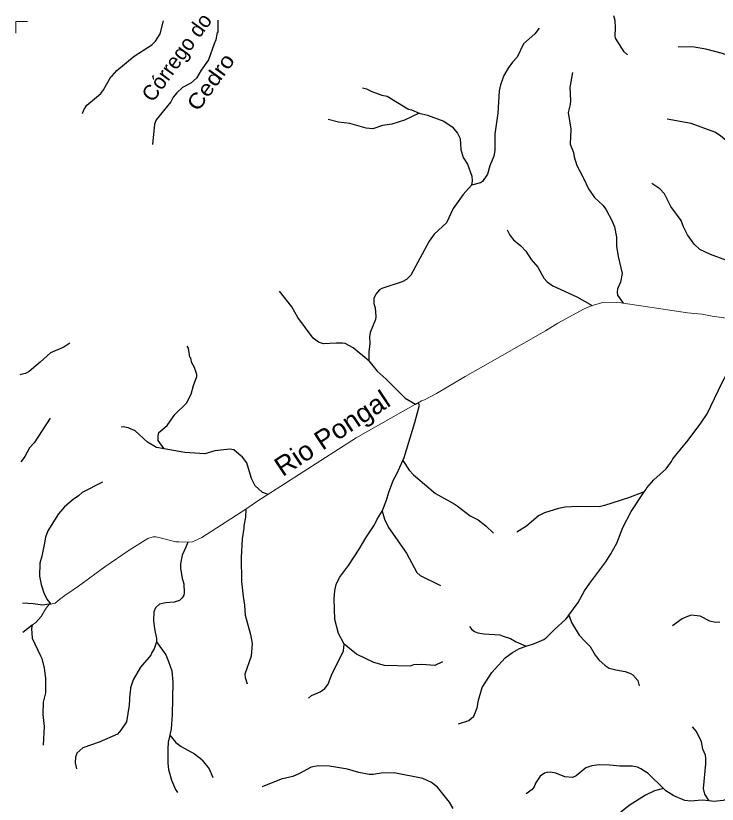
# Model space of a CAD drawing. Extents: x 317.8 to 344.1, y 7676.8 to 7704.8.
# Drawn here: x 317.793 to 321.463, y 7700.411 to 7704.539 of the extents above; entities that cross this region are included whole.
import ezdxf
from ezdxf.enums import TextEntityAlignment as Align

# ---------------------------------------------------------------- set-up
doc = ezdxf.new("R2010")
doc.units = 0
doc.header["$LTSCALE"] = 0.032
for name, color, linetype, lineweight in [('1', 7, 'Continuous', 13), ('63', 7, 'Continuous', 13), ('7', 7, 'Continuous', 25)]:
    doc.layers.add(name, color=color, linetype=linetype, lineweight=lineweight)
doc.layers.add('61', color=7, linetype='Continuous')

msp = doc.modelspace()

# ---------------------------------------------------------------- linework, layer by layer
at = {"layer": '1'}
for points in [[(320.8087, 7703.0226), (320.8641, 7703.0378), (320.9419, 7703.0395), (320.9717, 7703.035)], [(320.9717, 7703.035), (321.3079, 7702.9842), (321.3848, 7702.9759), (321.4363, 7702.9663), (321.7192, 7702.9269)], [(319.8989, 7702.5129), (319.9163, 7702.5228), (319.9317, 7702.5274), (319.9951, 7702.5615), (320.1438, 7702.6501), (320.2248, 7702.696), (320.5652, 7702.8889), (320.6296, 7702.9293), (320.7671, 7703.0045), (320.8087, 7703.0226)], [(319.1119, 7702.0323), (319.5748, 7702.3284), (319.8845, 7702.5047)], [(318.9971, 7701.9552), (319.0648, 7702.0022), (319.1119, 7702.0323)], [(318.6926, 7701.7822), (318.718, 7701.7847), (318.7659, 7701.8071), (318.9971, 7701.9552)], [(317.9761, 7701.4589), (317.9987, 7701.4639), (318.0212, 7701.4834), (318.0499, 7701.503), (318.1209, 7701.5517), (318.2595, 7701.6539), (318.3863, 7701.7416), (318.4847, 7701.8014), (318.5119, 7701.8104), (318.5274, 7701.8105), (318.6298, 7701.7845), (318.646, 7701.7839), (318.6926, 7701.7822)], [(317.9676, 7701.4577), (317.948, 7701.4315), (317.9265, 7701.393), (317.8972, 7701.362), (317.8781, 7701.3476)]]:
    msp.add_lwpolyline(points, dxfattribs=at)
at = {"layer": '63'}
msp.add_lwpolyline([(317.8546, 7704.5086), (317.793, 7704.5086), (317.793, 7704.4479)], dxfattribs=at)
at = {"layer": '7'}
for p, q in [((319.8845, 7702.5047), (319.8989, 7702.5129)), ((317.9761, 7701.4589), (317.9676, 7701.4577)), ((317.8781, 7701.3476), (317.8292, 7701.3107))]:
    msp.add_line(p, q, dxfattribs=at)
for points in [[(318.1428, 7704.0274), (318.1494, 7704.0465), (318.1642, 7704.0708), (318.215, 7704.1132), (318.2377, 7704.1322), (318.2523, 7704.1511), (318.2906, 7704.219), (318.2966, 7704.2255), (318.3218, 7704.2528), (318.4133, 7704.328), (318.5049, 7704.3878), (318.5233, 7704.407), (318.5477, 7704.4455), (318.5665, 7704.5133)], [(318.8502, 7704.5163), (318.8509, 7704.4524), (318.8476, 7704.451), (318.8402, 7704.4125), (318.8304, 7704.393), (318.8012, 7704.3085), (318.7633, 7704.2544), (318.7383, 7704.2121), (318.7097, 7704.1869), (318.6658, 7704.164), (318.6362, 7704.1362), (318.6173, 7704.1132), (318.604, 7704.089), (318.5276, 7703.994), (318.5192, 7703.9708), (318.5079, 7703.866)], [(320.9937, 7704.3354), (320.976, 7704.3499), (320.9305, 7704.4221), (320.9284, 7704.4316), (320.9317, 7704.476), (320.93, 7704.514), (320.9228, 7704.5386)], [(320.531, 7704.4749), (320.509, 7704.4441), (320.4496, 7704.3918), (320.4159, 7704.3231), (320.3916, 7704.2966), (320.3687, 7704.2648), (320.347, 7704.2264), (320.3296, 7704.1772), (320.3227, 7704.1461), (320.3149, 7704.0297), (320.2993, 7703.9192), (320.3001, 7703.8329), (320.2935, 7703.8033), (320.2729, 7703.7537), (320.2604, 7703.7093), (320.2358, 7703.6721), (320.2243, 7703.6647), (320.1772, 7703.6514)], [(322.3312, 7704.2681), (322.2484, 7704.2923), (322.1969, 7704.2991), (322.1875, 7704.3003), (321.904, 7704.2824), (321.7836, 7704.2898), (321.6788, 7704.2874), (321.6061, 7704.2973), (321.4911, 7704.341), (321.4044, 7704.3647), (321.3432, 7704.3753), (321.2586, 7704.3771)], [(320.7068, 7704.2426), (320.6913, 7704.1638), (320.6953, 7704.0959), (320.6936, 7704.0747), (320.6832, 7704.033), (320.6969, 7703.9454), (320.6946, 7703.8665), (320.712, 7703.8232), (320.7151, 7703.8009), (320.7281, 7703.7556), (320.7601, 7703.696), (320.7638, 7703.6891), (320.789, 7703.6337), (320.8211, 7703.5871), (320.8656, 7703.5456), (320.8825, 7703.5239), (320.9121, 7703.4674), (320.9249, 7703.434), (320.9365, 7703.3798), (320.9366, 7703.3334), (320.9445, 7703.2795), (320.9659, 7703.1891), (320.9577, 7703.1451), (320.941, 7703.1093), (320.9389, 7703.0921), (320.9415, 7703.0768), (320.9717, 7703.035)], [(319.6067, 7704.1613), (319.6284, 7704.157), (319.6552, 7704.1432), (319.7079, 7704.1239), (319.7359, 7704.1175), (319.8449, 7704.0522), (319.8472, 7704.0508), (319.8627, 7704.0474), (319.9038, 7704.0292)], [(319.9038, 7704.0292), (319.8629, 7704.0095), (319.8263, 7703.9919), (319.7611, 7703.9713), (319.7114, 7703.9639), (319.6606, 7703.9467), (319.6255, 7703.9501), (319.5403, 7703.975), (319.4823, 7703.9817), (319.4281, 7703.9956)], [(319.9038, 7704.0292), (319.9473, 7704.019), (320.0331, 7703.9867), (320.0762, 7703.9578), (320.1036, 7703.9248), (320.1182, 7703.8964), (320.1223, 7703.8394), (320.1341, 7703.7964), (320.1558, 7703.7624), (320.1786, 7703.6989), (320.1802, 7703.6756), (320.1772, 7703.6514)], [(321.8515, 7703.5299), (321.8095, 7703.5872), (321.7692, 7703.6355), (321.7581, 7703.6579), (321.751, 7703.6723), (321.6927, 7703.7578), (321.6541, 7703.7948), (321.612, 7703.8232), (321.5361, 7703.8629), (321.4804, 7703.9108), (321.4511, 7703.929), (321.3261, 7703.9755), (321.2015, 7703.9973)], [(320.1772, 7703.6514), (320.1474, 7703.6182), (320.1336, 7703.6028), (320.0823, 7703.5307), (320.0474, 7703.4545), (319.9823, 7703.3956), (319.9558, 7703.3597), (319.8599, 7703.1811), (319.8369, 7703.159), (319.8148, 7703.1461), (319.7075, 7703.112), (319.6962, 7703.1047), (319.6765, 7703.0815), (319.666, 7703.058), (319.6668, 7703.033), (319.6734, 7703.0091), (319.6773, 7702.9654), (319.6748, 7702.948), (319.6592, 7702.9096), (319.6472, 7702.8803), (319.644, 7702.8582), (319.6456, 7702.8232), (319.6399, 7702.7795), (319.6409, 7702.7322)], [(321.719, 7702.9874), (321.6852, 7703.0377), (321.654, 7703.1256), (321.6163, 7703.1747), (321.5571, 7703.2308), (321.5142, 7703.2584), (321.4285, 7703.2891), (321.3727, 7703.3145), (321.3419, 7703.3436), (321.3076, 7703.3918), (321.2859, 7703.4338), (321.275, 7703.4671), (321.2202, 7703.5408), (321.1867, 7703.6077), (321.1629, 7703.6324), (321.1217, 7703.6606)], [(320.3637, 7703.4178), (320.3783, 7703.39), (320.3976, 7703.3667), (320.4364, 7703.3343), (320.4616, 7703.3075), (320.4898, 7703.2623), (320.524, 7703.222), (320.556, 7703.1654), (320.5738, 7703.1459), (320.6037, 7703.1254), (320.7294, 7703.0674), (320.8087, 7703.0226)], [(319.6409, 7702.7322), (319.5579, 7702.8013), (319.5168, 7702.8229), (319.5019, 7702.8251), (319.4687, 7702.8241), (319.4037, 7702.822), (319.3767, 7702.8301), (319.3489, 7702.8514), (319.2696, 7702.9599), (319.2369, 7703.0153), (319.173, 7703.0967)], [(321.0817, 7702.0465), (321.0906, 7702.0598), (321.0955, 7702.0672), (321.1321, 7702.1088), (321.1954, 7702.1664), (321.2247, 7702.2052), (321.2317, 7702.2196), (321.3119, 7702.3172), (321.3783, 7702.406), (321.4103, 7702.4555), (321.4891, 7702.6198), (321.5102, 7702.657), (321.5748, 7702.7437), (321.6382, 7702.8112), (321.6696, 7702.8393), (321.7458, 7702.9232)], [(318.0752, 7702.8244), (318.0452, 7702.8038), (317.9751, 7702.7748), (317.9206, 7702.7247), (317.8623, 7702.6766), (317.8434, 7702.6657), (317.8192, 7702.6606), (317.8145, 7702.6596)], [(318.5688, 7702.2718), (318.5379, 7702.3144), (318.5372, 7702.3411), (318.5419, 7702.3575), (318.5849, 7702.3945), (318.625, 7702.4508), (318.6866, 7702.5105), (318.7115, 7702.5576), (318.7234, 7702.603), (318.7409, 7702.6505), (318.7402, 7702.6616), (318.7286, 7702.6974), (318.7142, 7702.7223), (318.7083, 7702.7457), (318.7035, 7702.7521), (318.6969, 7702.7979), (318.6905, 7702.8098)], [(319.6409, 7702.7322), (319.6841, 7702.6791), (319.7315, 7702.6359), (319.8305, 7702.537), (319.8845, 7702.5047)], [(319.8178, 7702.2102), (319.825, 7702.2262), (319.8818, 7702.4092), (319.9046, 7702.501), (319.8989, 7702.5129)], [(317.9725, 7702.4316), (317.8886, 7702.3038), (317.8645, 7702.2765), (317.8401, 7702.2315), (317.8209, 7702.205), (317.8195, 7702.203)], [(318.5688, 7702.2718), (318.5286, 7702.2791), (318.4824, 7702.307), (318.4175, 7702.3654), (318.3804, 7702.381), (318.3556, 7702.3866), (318.3441, 7702.3852)], [(319.1119, 7702.0323), (319.0828, 7702.0447), (319.045, 7702.0775), (319.0258, 7702.1164), (319.0012, 7702.1983), (318.9795, 7702.2271), (318.9605, 7702.2436), (318.9346, 7702.266), (318.9129, 7702.27), (318.8341, 7702.2608), (318.7817, 7702.2458), (318.6771, 7702.2523), (318.5688, 7702.2718)], [(319.71, 7701.9458), (319.7335, 7702.0033), (319.7452, 7702.0447), (319.769, 7702.1086), (319.7871, 7702.1415), (319.8178, 7702.2102)], [(319.8178, 7702.2102), (319.8517, 7702.1604), (319.8738, 7702.1356), (319.989, 7702.0383), (320.0861, 7701.9829), (320.1019, 7701.9739), (320.1698, 7701.9207), (320.2126, 7701.9005), (320.2527, 7701.8692), (320.292, 7701.8301)], [(318.2463, 7702.0974), (318.1399, 7702.0429), (318.1218, 7702.0259), (318.0928, 7702.0066), (318.0484, 7701.9672), (318.0163, 7701.9306), (317.9611, 7701.8426), (317.9489, 7701.8088), (317.9431, 7701.7796), (317.9291, 7701.7089), (317.9195, 7701.6727), (317.9178, 7701.6056), (317.9264, 7701.5616), (317.9398, 7701.5179), (317.9563, 7701.485), (317.9761, 7701.4589)], [(321.0817, 7702.0465), (321.0816, 7702.0465), (320.9996, 7702.0146), (320.8742, 7701.9743), (320.8456, 7701.9686), (320.7318, 7701.9703), (320.6683, 7701.9654), (320.6335, 7701.9588), (320.5589, 7701.9366), (320.5276, 7701.9209), (320.4658, 7701.8662), (320.4142, 7701.8358)], [(320.687, 7701.4002), (320.7358, 7701.4662), (320.7688, 7701.528), (320.796, 7701.569), (320.8807, 7701.6796), (320.9072, 7701.7216), (320.9372, 7701.7784), (320.969, 7701.8599), (321.0122, 7701.9428), (321.0817, 7702.0465)], [(318.9971, 7701.9552), (318.9952, 7701.9141), (318.9856, 7701.8691), (318.9861, 7701.8562), (318.9773, 7701.8003), (318.9724, 7701.7025), (318.9741, 7701.5775), (318.9822, 7701.4976), (318.9903, 7701.4523), (318.9937, 7701.4015), (319.0214, 7701.2992), (319.0295, 7701.2529), (319.0244, 7701.1867), (318.9912, 7701.0925), (318.9928, 7701.0748), (319.0035, 7701.0412)], [(319.5104, 7701.248), (319.4809, 7701.3044), (319.4631, 7701.3778), (319.4582, 7701.4865), (319.463, 7701.5306), (319.4698, 7701.561), (319.4867, 7701.5975), (319.5343, 7701.6607), (319.5901, 7701.7462), (319.6243, 7701.8059), (319.6704, 7701.8739), (319.6846, 7701.9039), (319.71, 7701.9458)], [(319.71, 7701.9458), (319.7222, 7701.9037), (319.743, 7701.8601), (319.8373, 7701.7246), (319.8922, 7701.6249), (319.9086, 7701.6086), (320.0149, 7701.5555)], [(318.6926, 7701.7822), (318.6836, 7701.7573), (318.6632, 7701.715), (318.6546, 7701.6686), (318.6546, 7701.646), (318.6628, 7701.5928), (318.6724, 7701.564), (318.6742, 7701.5181), (318.6716, 7701.5049), (318.6643, 7701.4919), (318.6503, 7701.4773), (318.6223, 7701.4682), (318.5779, 7701.4657), (318.5455, 7701.4575), (318.5301, 7701.4446), (318.5245, 7701.4399), (318.5159, 7701.4173), (318.5144, 7701.3732), (318.5185, 7701.3297), (318.5289, 7701.2787), (318.5293, 7701.2603)], [(317.9676, 7701.4577), (317.933, 7701.4527), (317.8841, 7701.4608), (317.8275, 7701.464)], [(320.464, 7701.2377), (320.5077, 7701.2518), (320.5556, 7701.2731), (320.5702, 7701.2836), (320.61, 7701.3241), (320.6715, 7701.3792), (320.6814, 7701.3926), (320.687, 7701.4002)], [(320.687, 7701.4002), (320.69, 7701.3918), (320.7006, 7701.3623), (320.7402, 7701.2967), (320.7731, 7701.2622), (320.7978, 7701.2362), (320.8254, 7701.1912), (320.8444, 7701.1666), (320.8769, 7701.1363), (320.8982, 7701.1239), (320.9328, 7701.1138), (320.9821, 7701.106), (321.0087, 7701.0957), (321.0208, 7701.0874), (321.0472, 7701.0592), (321.054, 7701.0314)], [(321.4771, 7701.3646), (321.4536, 7701.3622), (321.4237, 7701.3697), (321.3733, 7701.3956), (321.3272, 7701.4004), (321.2987, 7701.3895), (321.2799, 7701.3823), (321.2293, 7701.3452)], [(317.8781, 7701.3476), (317.8746, 7701.3312), (317.8792, 7701.28), (317.922, 7701.1872), (317.9285, 7701.173), (317.9422, 7701.123), (317.9479, 7701.07), (317.9479, 7700.9947), (317.936, 7700.9457), (317.9344, 7700.88), (317.9423, 7700.8185), (317.9358, 7700.7201)], [(320.1665, 7701.3411), (320.1793, 7701.3251), (320.1933, 7701.3154), (320.2102, 7701.3088), (320.2419, 7701.3029), (320.3263, 7701.2972), (320.3439, 7701.2913), (320.3821, 7701.2784), (320.4112, 7701.261), (320.464, 7701.2377)], [(318.5293, 7701.2603), (318.5177, 7701.2249), (318.5046, 7701.205), (318.4996, 7701.1911), (318.4451, 7701.1283), (318.407, 7701.0622), (318.3939, 7701.0199), (318.392, 7700.9961), (318.3889, 7700.9902), (318.3871, 7700.9291), (318.3725, 7700.8426), (318.3434, 7700.7977), (318.3251, 7700.778), (318.2298, 7700.7349), (318.1442, 7700.7064), (318.113, 7700.6777), (318.1061, 7700.6576), (318.1037, 7700.6276), (318.111, 7700.5962)], [(318.5293, 7701.2603), (318.5773, 7701.1931), (318.5929, 7701.1587), (318.6089, 7701.1093), (318.6139, 7701.0495), (318.6105, 7700.8786), (318.6056, 7700.8057), (318.5987, 7700.7725)], [(319.3238, 7700.9662), (319.3395, 7700.9801), (319.3853, 7700.9991), (319.4098, 7701.0165), (319.4269, 7701.0401), (319.4454, 7701.0865), (319.5086, 7701.2134), (319.5104, 7701.248)], [(320.0263, 7701.1569), (319.9849, 7701.1365), (319.9175, 7701.1422), (319.8742, 7701.1398), (319.8568, 7701.1341), (319.7219, 7701.1365), (319.6672, 7701.1532), (319.5752, 7701.1969), (319.5104, 7701.248)], [(320.11, 7700.8308), (320.1631, 7700.8483), (320.189, 7700.8723), (320.2079, 7700.9151), (320.2137, 7700.9556), (320.2341, 7701.0224), (320.2833, 7701.1003), (320.3544, 7701.1768), (320.3799, 7701.1962), (320.3916, 7701.2051), (320.428, 7701.2261), (320.464, 7701.2377)], [(321.4203, 7700.4284), (321.3979, 7700.4636), (321.3914, 7700.4927), (321.4044, 7700.6223), (321.4044, 7700.6523), (321.4013, 7700.668), (321.3883, 7700.6993), (321.3804, 7700.737), (321.354, 7700.7922), (321.3336, 7700.8162)], [(318.5987, 7700.7725), (318.591, 7700.7355), (318.5909, 7700.718), (318.5878, 7700.714), (318.5878, 7700.6723), (318.5878, 7700.6256), (318.5917, 7700.5924), (318.6082, 7700.5363), (318.6295, 7700.4874), (318.6391, 7700.4723)], [(318.5987, 7700.7725), (318.6307, 7700.7341), (318.6588, 7700.713), (318.7284, 7700.6745), (318.7657, 7700.644), (318.7682, 7700.641), (318.8047, 7700.5966), (318.8233, 7700.5506)], [(320.0824, 7700.3883), (320.0632, 7700.4208), (319.999, 7700.4994), (319.968, 7700.5237), (319.9224, 7700.5448), (319.7731, 7700.5757), (319.7056, 7700.5741), (319.6627, 7700.566), (319.6416, 7700.5668), (319.5881, 7700.5771), (319.5282, 7700.5936), (319.435, 7700.6092), (319.376, 7700.6116), (319.3392, 7700.6044), (319.2782, 7700.5713), (319.243, 7700.5561), (319.1824, 7700.5422), (319.0825, 7700.5025)], [(321.1825, 7700.4923), (321.1015, 7700.5713), (321.0627, 7700.5966), (321.0461, 7700.6041), (321.0188, 7700.6107), (320.9538, 7700.6092), (320.9014, 7700.6156), (320.8463, 7700.6164), (320.8072, 7700.6115), (320.775, 7700.601), (320.7247, 7700.5592), (320.7061, 7700.5508), (320.6656, 7700.5538), (320.6181, 7700.5738), (320.591, 7700.579), (320.5719, 7700.5774), (320.5587, 7700.5726), (320.5364, 7700.5578), (320.5121, 7700.5206), (320.5048, 7700.5011), (320.4953, 7700.4882), (320.4631, 7700.465)], [(321.7949, 7700.5581), (321.7781, 7700.5437), (321.7321, 7700.5167), (321.6019, 7700.465), (321.4946, 7700.4304), (321.4454, 7700.4256), (321.4203, 7700.4284)], [(321.1825, 7700.4923), (321.1352, 7700.4814), (321.0885, 7700.4585), (321.0025, 7700.4033), (320.9015, 7700.3228), (320.8374, 7700.2814), (320.8234, 7700.2775)], [(321.4203, 7700.4284), (321.3853, 7700.4324), (321.3241, 7700.4275), (321.2931, 7700.4297), (321.2358, 7700.4547), (321.1939, 7700.4812), (321.1825, 7700.4923)]]:
    msp.add_lwpolyline(points, dxfattribs=at)

# ---------------------------------------------------------------- texts
at = {"layer": '61'}
msp.add_text('Córrego do', height=0.08, rotation=54.027, dxfattribs=at).set_placement((318.6671, 7704.2986), align=Align.CENTER)
for s, height, rotation, width, p in [('Cedro', 0.08, 54.027, 1.15, (318.845, 7704.1694)), ('Rio Pongal', 0.1, 33.453, 1.05, (319.4756, 7702.3123))]:
    msp.add_text(s, height=height, rotation=rotation, dxfattribs=dict(at, width=width)).set_placement(p, align=Align.CENTER)

doc.saveas('drawing.dxf')
